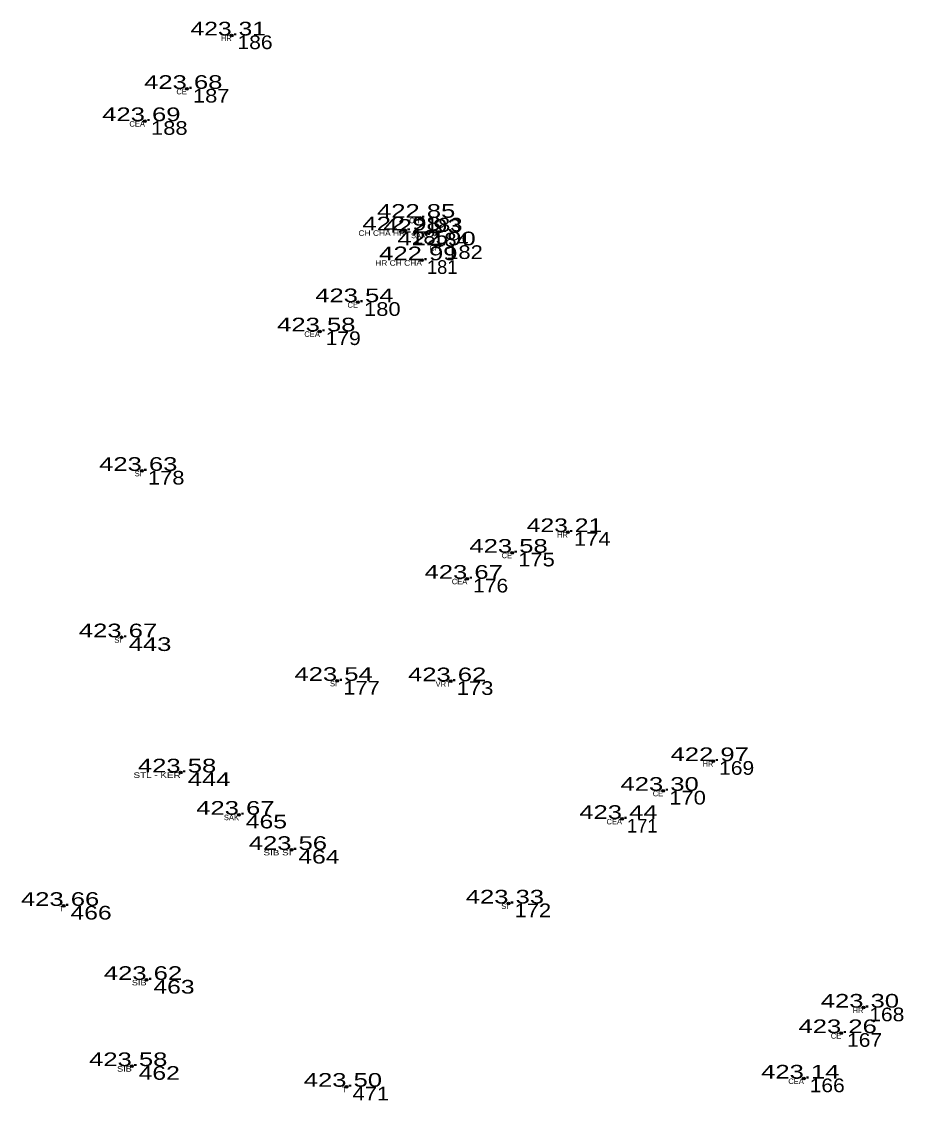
# Model space of a CAD drawing. Extents: x -639373 to -639056, y -1138651 to -1138359.
# Drawn here: x -639181.4 to -639133, y -1138586.4 to -1138527.2 of the extents above; entities that cross this region are included whole.
import ezdxf
from ezdxf.enums import TextEntityAlignment as Align

# ---------------------------------------------------------------- set-up
doc = ezdxf.new("R2010")
doc.units = 0
doc.header["$LTSCALE"] = 0.3
doc.header["$PDMODE"] = 32
doc.header["$PDSIZE"] = 0.15
for name, color, linetype in [('11', 7, 'Continuous'), ('12', 7, 'Continuous'), ('13', 7, 'Continuous'), ('14', 7, 'Continuous'), ('57', 7, 'Continuous')]:
    doc.layers.add(name, color=color, linetype=linetype)

msp = doc.modelspace()

# ---------------------------------------------------------------- linework, layer by layer
at = {"layer": '11'}
for p in [(-639169.89, -1138527.94), (-639172.35, -1138530.87), (-639174.65, -1138532.64), (-639159.57, -1138537.94), (-639160.37, -1138538.63), (-639159.22, -1138538.76), (-639158.45, -1138539.45), (-639159.45, -1138540.27), (-639162.96, -1138542.57), (-639165.05, -1138544.17), (-639174.82, -1138551.82), (-639151.44, -1138555.18), (-639154.5, -1138556.31), (-639156.96, -1138557.74), (-639175.93, -1138560.95), (-639164.1, -1138563.34), (-639157.87, -1138563.36), (-639143.46, -1138567.74), (-639172.69, -1138568.36), (-639146.21, -1138569.37), (-639169.49, -1138570.68), (-639148.47, -1138570.91), (-639166.61, -1138572.61), (-639179.11, -1138575.68), (-639154.7, -1138575.55), (-639174.56, -1138579.74), (-639135.22, -1138581.26), (-639136.44, -1138582.66), (-639175.37, -1138584.47), (-639138.49, -1138585.15), (-639163.59, -1138585.6)]:
    msp.add_point(p, dxfattribs=at)

# ---------------------------------------------------------------- texts
at = {"layer": '12', "width": 1.4}
for s, p in [('422.85 ', (-639159.57, -1138537.94)), ('422.98 ', (-639160.37, -1138538.63)), ('422.90 ', (-639158.45, -1138539.45)), ('422.99 ', (-639159.45, -1138540.27)), ('423.58 ', (-639172.69, -1138568.36)), ('423.67 ', (-639169.49, -1138570.68))]:
    msp.add_text(s, height=0.75, dxfattribs=at).set_placement(p, align=Align.CENTER)
at = {"layer": '13'}
for s, width, p in [(' 186', 1.15, (-639169.89, -1138528.69)), (' 187', 1.2, (-639172.35, -1138531.62)), (' 188', 1.2, (-639174.65, -1138533.39)), (' 183', 1.2, (-639159.57, -1138538.69)), (' 185', 1.2, (-639160.37, -1138539.38)), (' 184', 1.2, (-639159.22, -1138539.51)), (' 182', 1.2, (-639158.45, -1138540.2)), (' 180', 1.2, (-639162.96, -1138543.32)), (' 179', 1.15, (-639165.05, -1138544.92)), (' 178', 1.2, (-639174.82, -1138552.57)), (' 174', 1.2, (-639151.44, -1138555.93)), (' 175', 1.2, (-639154.5, -1138557.06)), (' 176', 1.15, (-639156.96, -1138558.49)), (' 443', 1.4, (-639175.93, -1138561.7)), (' 177', 1.2, (-639164.1, -1138564.09)), (' 173', 1.2, (-639157.87, -1138564.11)), (' 169', 1.15, (-639143.46, -1138568.49)), (' 444', 1.4, (-639172.69, -1138569.11)), (' 170', 1.2, (-639146.21, -1138570.12)), (' 465', 1.35, (-639169.49, -1138571.43)), (' 464', 1.35, (-639166.61, -1138573.36)), (' 466', 1.35, (-639179.11, -1138576.43)), (' 172', 1.2, (-639154.7, -1138576.3)), (' 463', 1.35, (-639174.56, -1138580.49)), (' 168', 1.15, (-639135.22, -1138582.01)), (' 167', 1.15, (-639136.44, -1138583.41)), (' 462', 1.35, (-639175.37, -1138585.22)), (' 166', 1.15, (-639138.49, -1138585.9)), (' 471', 1.2, (-639163.59, -1138586.35))]:
    msp.add_text(s, height=0.75, dxfattribs=dict(at, width=width)).set_placement(p)
for s, p in [(' 181', (-639159.45, -1138541.02)), (' 171', (-639148.47, -1138571.66))]:
    msp.add_text(s, height=0.75, dxfattribs=at).set_placement(p)
at = {"layer": '14'}
for s, width, p in [('423.31 ', 1.35, (-639169.889, -1138527.94)), ('423.68 ', 1.4, (-639172.35, -1138530.87)), ('423.69 ', 1.4, (-639174.65, -1138532.64)), ('422.93 ', 1.4, (-639159.22, -1138538.76)), ('423.54 ', 1.4, (-639162.96, -1138542.57)), ('423.58 ', 1.4, (-639165.05, -1138544.17)), ('423.63 ', 1.4, (-639174.82, -1138551.82)), ('423.21 ', 1.35, (-639151.439, -1138555.18)), ('423.58 ', 1.4, (-639154.5, -1138556.31)), ('423.67 ', 1.4, (-639156.96, -1138557.74)), ('423.67 ', 1.4, (-639175.93, -1138560.95)), ('423.54 ', 1.4, (-639164.1, -1138563.34)), ('423.62 ', 1.4, (-639157.87, -1138563.36)), ('422.97 ', 1.4, (-639143.46, -1138567.74)), ('423.30 ', 1.4, (-639146.21, -1138569.37)), ('423.44 ', 1.4, (-639148.47, -1138570.91)), ('423.56 ', 1.4, (-639166.609, -1138572.61)), ('423.66 ', 1.4, (-639179.109, -1138575.68)), ('423.33 ', 1.4, (-639154.7, -1138575.55)), ('423.62 ', 1.4, (-639174.56, -1138579.74)), ('423.30 ', 1.4, (-639135.22, -1138581.26)), ('423.26 ', 1.4, (-639136.439, -1138582.66)), ('423.58 ', 1.4, (-639175.37, -1138584.47)), ('423.14 ', 1.4, (-639138.49, -1138585.15)), ('423.50 ', 1.4, (-639163.59, -1138585.6))]:
    msp.add_text(s, height=0.75, dxfattribs=dict(at, width=width)).set_placement(p, align=Align.CENTER)
at = {"layer": '57'}
for s, width, p in [('HR', 0.85, (-639169.889, -1138528.24)), ('CE', 0.9, (-639172.35, -1138531.17)), ('CH', 0.8, (-639159.569, -1138538.24)), ('CH CHA HR', 1.15, (-639160.369, -1138538.93)), ('CH', 0.8, (-639158.449, -1138539.75)), ('HR CH CHA', 1.15, (-639159.45, -1138540.57)), ('CE', 0.9, (-639162.96, -1138542.87)), ('SI', 1.05, (-639174.82, -1138552.12)), ('HR', 0.85, (-639151.439, -1138555.48)), ('CE', 0.9, (-639154.5, -1138556.61)), ('SI', 1.05, (-639175.93, -1138561.25)), ('SI', 1.05, (-639164.1, -1138563.64)), ('HR', 0.85, (-639143.459, -1138568.04)), ('STL - KER', 1.35, (-639172.689, -1138568.66)), ('CE', 0.9, (-639146.21, -1138569.67)), ('SIB SI', 1.35, (-639166.61, -1138572.91)), ('T', 0.85, (-639179.11, -1138575.98)), ('SI', 1.05, (-639154.7, -1138575.85)), ('SIB', 1.25, (-639174.559, -1138580.04)), ('HR', 0.85, (-639135.219, -1138581.56)), ('CE', 0.9, (-639136.44, -1138582.96)), ('SIB', 1.25, (-639175.369, -1138584.77)), ('T', 0.85, (-639163.59, -1138585.9))]:
    msp.add_text(s, height=0.3, dxfattribs=dict(at, width=width)).set_placement(p, align=Align.RIGHT)
for s, p in [('CEA', (-639174.65, -1138532.94)), ('SAK', (-639159.219, -1138539.06)), ('CEA', (-639165.05, -1138544.47)), ('CEA', (-639156.96, -1138558.04)), ('VRT', (-639157.87, -1138563.66)), ('SAK', (-639169.489, -1138570.98)), ('CEA', (-639148.47, -1138571.21)), ('CEA', (-639138.49, -1138585.45))]:
    msp.add_text(s, height=0.3, dxfattribs=at).set_placement(p, align=Align.RIGHT)

doc.saveas('drawing.dxf')
